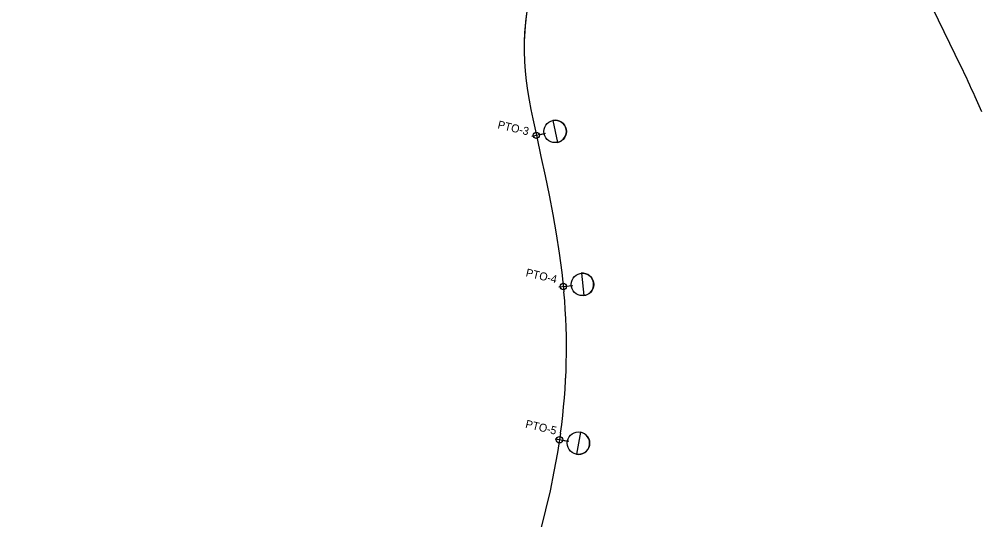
# Model space of a CAD drawing. Extents: x 0 to 511877, y 0 to 6211921.
# Drawn here: x 511654.3 to 511804.6, y 6211693.3 to 6211771.4 of the extents above; entities that cross this region are included whole.
import ezdxf

# ---------------------------------------------------------------- set-up
doc = ezdxf.new("R2010")
doc.units = 0
for name, color, linetype in [('Help', 7, 'Continuous'), ('TV_U_LYS_Ledn-', 7, 'Continuous'), ('TV_U_LYS_Mastenummer', 7, 'Continuous'), ('TV_U_LYS_Nyx330-Trafiksti', 7, 'Continuous')]:
    doc.layers.add(name, color=color, linetype=linetype)

msp = doc.modelspace()

# ---------------------------------------------------------------- linework, layer by layer
at = {"layer": 'Help'}
for p, q in [((511801.3, 6211764.11), (511784.63, 6211798.45)), ((511804.55, 6211756.98), (511803.52, 6211759.31)), ((511734.33, 6211753.16), (511736.47, 6211753.62)), ((511738.54, 6211729.63), (511740.72, 6211729.85)), ((511737.94, 6211705.89), (511740.1, 6211705.54))]:
    msp.add_line(p, q, dxfattribs=at)
for points in [[(511733.17, 6211764.88), (511733.17, 6211764.85), (511733.28, 6211763.33), (511733.45, 6211761.8), (511733.66, 6211760.29), (511733.9, 6211758.8), (511734.18, 6211757.33), (511734.47, 6211755.89), (511734.77, 6211754.47), (511735.08, 6211753.06), (511735.74, 6211750.01), (511736.39, 6211746.98), (511737.01, 6211743.95), (511737.6, 6211740.93), (511738.14, 6211737.91), (511738.61, 6211734.9), (511739.01, 6211731.89), (511739.33, 6211728.85)], [(511738.8, 6211706.79), (511738.33, 6211703.78), (511737.78, 6211700.79), (511737.16, 6211697.8), (511736.48, 6211694.82), (511735.75, 6211691.83), (511734.98, 6211688.83), (511734.18, 6211685.83), (511733.37, 6211682.82), (511712.7, 6211606.36), (511712.29, 6211604.86), (511711.88, 6211603.37), (511711.46, 6211601.9), (511711.03, 6211600.45), (511710.58, 6211599.01), (511710.11, 6211597.6), (511709.61, 6211596.22), (511709.06, 6211594.83)]]:
    msp.add_lwpolyline(points, dxfattribs=at)
for centre, radius, start, end in [((511554.61, 6212123.21), 355, 263.5186, 295.1994), ((511771.57, 6211766.89), 38.45, 113.1329, 182.9937), ((511668.37, 6211699.6), 147.75, 23.8374, 25.8873), ((511643.18, 6211720.15), 96.55, 352.0473, 5.171)]:
    msp.add_arc(centre, radius, start, end, dxfattribs=at)
at = {"layer": 'TV_U_LYS_Ledn-'}
for points in [[(511733.17, 6211764.88), (511733.17, 6211764.85), (511733.28, 6211763.33), (511733.45, 6211761.8), (511733.66, 6211760.29), (511733.9, 6211758.8), (511734.18, 6211757.33), (511734.47, 6211755.89), (511734.77, 6211754.47), (511735.08, 6211753.06), (511735.74, 6211750.01), (511736.39, 6211746.98), (511737.01, 6211743.95), (511737.6, 6211740.93), (511738.14, 6211737.91), (511738.61, 6211734.9), (511739.01, 6211731.89), (511739.33, 6211728.85)], [(511738.8, 6211706.8), (511738.33, 6211703.78), (511737.78, 6211700.79), (511737.16, 6211697.8), (511736.48, 6211694.82), (511735.75, 6211691.83), (511734.98, 6211688.83), (511734.18, 6211685.83), (511733.37, 6211682.82), (511712.7, 6211606.36), (511712.29, 6211604.86), (511711.88, 6211603.37), (511711.46, 6211601.9), (511711.03, 6211600.45), (511710.58, 6211599.01), (511710.11, 6211597.6), (511709.61, 6211596.22), (511709.06, 6211594.83)]]:
    msp.add_lwpolyline(points, dxfattribs=at)
for centre, radius, start, end in [((511771.57, 6211766.89), 38.45, 110.2939, 182.9937), ((511643.18, 6211720.15), 96.55, 352.0453, 5.173)]:
    msp.add_arc(centre, radius, start, end, dxfattribs=at)
at = {"layer": 'TV_U_LYS_Nyx330-Trafiksti'}
for p, q in [((511737.62, 6211755.62), (511738.31, 6211752.19)), ((511737.62, 6211755.62), (511737.62, 6211755.62)), ((511735.51, 6211753.41), (511736.25, 6211753.56)), ((511742.05, 6211731.76), (511742.42, 6211728.28)), ((511742.05, 6211731.76), (511742.05, 6211731.76)), ((511739.74, 6211729.75), (511740.49, 6211729.83)), ((511741.91, 6211706.95), (511741.28, 6211703.51)), ((511741.91, 6211706.95), (511741.91, 6211706.95)), ((511739.13, 6211705.68), (511739.87, 6211705.55))]:
    msp.add_line(p, q, dxfattribs=at)
for centre, radius in [((511737.96, 6211753.91), 1.75), ((511735.02, 6211753.31), 0.5), ((511742.23, 6211730.02), 1.75), ((511739.24, 6211729.7), 0.5), ((511738.64, 6211705.77), 0.5), ((511741.59, 6211705.23), 1.75)]:
    msp.add_circle(centre, radius, dxfattribs=at)
for centre, start, end in [((511737.96, 6211753.91), 281.4684, 101.3984), ((511742.23, 6211730.02), 276.0922, 96.0222), ((511741.59, 6211705.23), 259.6468, 79.5769)]:
    msp.add_arc(centre, 1.75, start, end, dxfattribs=at)

# ---------------------------------------------------------------- texts
at = {"layer": 'TV_U_LYS_Mastenummer'}
for s, p in [('PTO-3', (511728.9, 6211754.42)), ('PTO-4', (511733.29, 6211731.31)), ('PTO-5', (511733.23, 6211707.68))]:
    msp.add_text(s, height=1.25, rotation=346.664, dxfattribs=at).set_placement(p)

doc.saveas('drawing.dxf')
